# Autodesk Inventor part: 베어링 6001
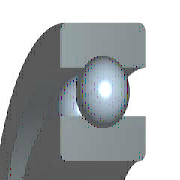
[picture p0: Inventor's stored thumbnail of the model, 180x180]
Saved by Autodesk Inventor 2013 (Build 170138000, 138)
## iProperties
IsCustomPart: 1
Created: 2009-02
Part Number: 베어링 6001
Material: 강, 연강
Description: 깊은 그루브 볼 베어링
Document SubType Name: Modeling
Standard: KS B 2023
Standards Organization: KS
Language: ko-KR
Size Designation: 6001 - 12 x 28 x 8
Categories: <MemberInstance><Categories><Category DisplayName="샤프트 부품" InternalName="7f7aeb1f-a693-4053-b835-cee3144e0d98" Mnemonic="SHFT"><Category DisplayName="베어링" Inter
Density: 1 g/cm^3
Engineer: 한국산업디자인학원-SeoGD™
Author: 진현석
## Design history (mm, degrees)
sketch "스케치" dims "d0" = 4.16 (= -0.26 x WD + 0.26 x BD)
  geometry: L1 (1.92, 10)-(6.08, 10); L2 (4, 10)-(4, 7.92); L3 (4, 10)-(4, 12.08); L4 (2.454, 8.608)-(0, 8.608); L5 (0, 6)-(8, 6); L6 (2.454, 11.392)-(0, 11.392); L7 (0, 14)-(8, 14); L8 (8, 6)-(8, 8.608); L9 (5.546, 8.608)-(8, 8.608); L10 (5.546, 11.392)-(8, 11.392); L11 (8, 14)-(8, 11.392); L12 (-1.4, 0)-(8.4, 0) reference; L13 (0, -0.3)-(0, 5.3) reference
  constraints: 22 end point, 4 point on line, 2 collinear, 2 perpendicular, 2 symmetric about line, 1 midpoint, 1 parallel, 14 other
  dimensions: "d9" = 12 diameter of L5 L12 (= WD); "d11" = 28 diameter of L7 L12 (= BD); "d12" = 8 distance between parallel lines of L8 L13 (= KB); "d13" = 17.216 diameter of L9 L12 (= 0.326 x BD + 0.674 x WD)
revolve "본체" stored, may be unused: angle "d6" = 90 deg
revolve "볼" stored, may be unused: angle "d7" = 90 deg
pattern_circular "IDS_ARRAYBALL[SIMPL:T]" dims angle "d3" = 360 deg
body "Solid1"
fillet "모깎기1" dims "d1" = 0.3 (= KRS)
other parameters: "WD" = 12 [user parameter; used in 5 equation terms], "BD" = 28 [user parameter; used in 5 equation terms], "KB" = 8 [user parameter; used in 1 equation term], "KRS" = 0.3 [user parameter; used in 1 equation term], "d4" = 0, "d5" = 0, "d8" = 0, "d14" = 0, "d15" = 0, "BBA" = 0 [user parameter], "BC0" = 2360000 [user parameter], "BC" = 5070000 [user parameter], "BR" = 14 (= 0.5 x BD) [user parameter], "WR" = 6 (= 0.5 x WD) [user parameter]
